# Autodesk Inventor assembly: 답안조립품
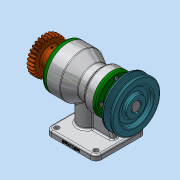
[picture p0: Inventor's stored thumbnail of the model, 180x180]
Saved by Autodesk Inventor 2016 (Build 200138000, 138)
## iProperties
Created: 2019-01
Part Number: 답안조립품
Material: 일반
Document SubType Name: Assembly
Designer: Administrator
Author: Administrator
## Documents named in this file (15)
- C:\Users\Administrator\Desktop\490107V1022\답안조립품.iam
- C:\Users\Administrator\Desktop\490107V1022\본체.ipt
- C:\Users\Administrator\Desktop\490107V1022\축.ipt
- C:\Users\Administrator\Desktop\490107V1022\키 6 x 6 x 18.ipt
- C:\Users\Administrator\Desktop\490107V1022\키 5 x 5 x 20.ipt
- C:\Users\Administrator\Desktop\490107V1022\뒤커버.ipt
- C:\Users\Administrator\Desktop\490107V1022\볼트 M4.ipt
- C:\Users\Administrator\Desktop\490107V1022\오일 실 17 30 8.ipt
- C:\Users\Administrator\Desktop\490107V1022\V-벨트풀리.ipt
- C:\Users\Administrator\Desktop\490107V1022\베어링 6203.ipt
- C:\Users\Administrator\Desktop\490107V1022\베어링 6205.ipt
- C:\Users\Administrator\Desktop\490107V1022\앞커버.ipt
- C:\Users\Administrator\Desktop\490107V1022\오일 실 25 38 8.ipt
- C:\Users\Administrator\Desktop\490107V1022\스퍼기어.ipt
- C:\Users\Administrator\Desktop\490107V1022\멈춤나사 M3.ipt
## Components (1 placed, 1 different names)
1. V-벨트풀리:1
